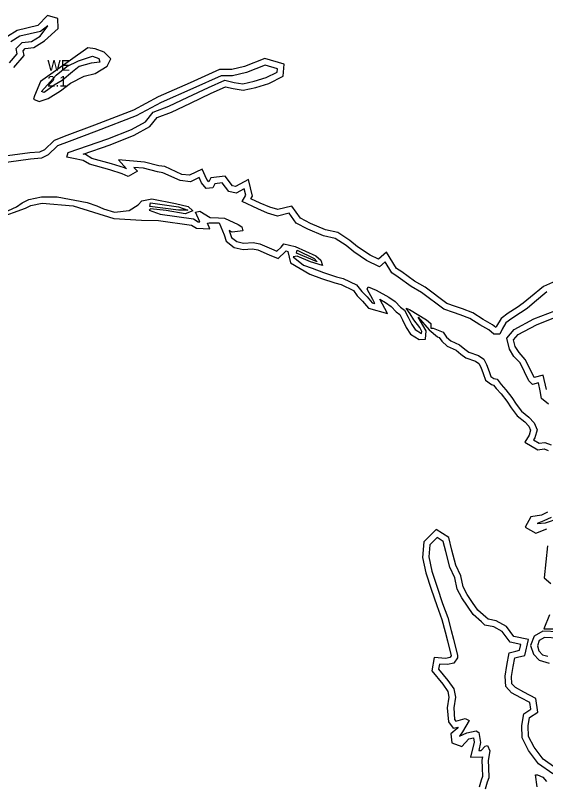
# Model space of a CAD drawing. Extents: x 2160437 to 2172832, y 205694 to 212444.
# Drawn here: x 2162368.8 to 2162620.3, y 210230.1 to 210593.8 of the extents above; entities that cross this region are included whole.
import ezdxf

# ---------------------------------------------------------------- set-up
doc = ezdxf.new("R2010")
doc.units = 0
for name, color, linetype in [('RD_EX_H2O', 7, 'Continuous'), ('RD_EX_H2O_Pond', 7, 'Continuous'), ('RD_EX_H2O_txCode', 7, 'Continuous'), ('RD_EX_VEG_ShrubLine', 7, 'Continuous')]:
    doc.layers.add(name, color=color, linetype=linetype)

msp = doc.modelspace()

# ---------------------------------------------------------------- linework, layer by layer
at = {"layer": 'RD_EX_H2O'}
for points in [[(2162366.04, 210571.34), (2162369.65, 210575.55), (2162369.15, 210578.05), (2162372.03, 210580.91), (2162376.47, 210581.45), (2162380.52, 210583.96), (2162384.23, 210588.79), (2162380.74, 210586.21), (2162370.89, 210583.87), (2162366.65, 210581.2)], [(2162535.39, 210477.67), (2162529.25, 210481.66), (2162525.66, 210484.63), (2162520.48, 210488.07), (2162514.92, 210489.34), (2162507.55, 210492.44), (2162501.91, 210495.25), (2162498.67, 210499.98), (2162493.1, 210498.63), (2162488.42, 210500.1), (2162483.72, 210502.07), (2162476.33, 210505.54), (2162478.05, 210508.61), (2162477.33, 210511.57), (2162473.57, 210509.58), (2162470.03, 210510.38), (2162466.9, 210514.4), (2162463.37, 210514), (2162462.4, 210512.09), (2162459.33, 210511.66), (2162457.05, 210514.35), (2162455.9, 210516.9), (2162451.92, 210514.95), (2162446.87, 210515.46), (2162438.76, 210519.18), (2162436.17, 210519.55), (2162429.52, 210521.31), (2162425.01, 210521.7), (2162426.66, 210519.88), (2162422.31, 210517.38), (2162419.48, 210518.7), (2162413.52, 210520.51), (2162403.88, 210523.24), (2162400.88, 210524.99), (2162396.28, 210525.96), (2162393.21, 210526.6), (2162393.87, 210528.76), (2162412.68, 210535.21), (2162423.85, 210539.71), (2162430.52, 210543.4), (2162434.19, 210547.88), (2162441.62, 210550.7), (2162450.52, 210554.95), (2162460.46, 210559.64), (2162468.2, 210563.04), (2162472.61, 210562.03), (2162476.69, 210561.36), (2162482, 210562.53), (2162487.81, 210564.27), (2162492.99, 210566.88), (2162493.11, 210568.51), (2162487.25, 210570.15), (2162478.33, 210566.68), (2162471.73, 210565.18), (2162466.32, 210565.13), (2162452.91, 210559.1), (2162437.86, 210552.49), (2162426.04, 210546.11), (2162407.33, 210538.96), (2162394.31, 210534.08), (2162388.8, 210531.92), (2162384.26, 210527.64), (2162381.1, 210526.05), (2162375.89, 210525.67), (2162360.88, 210523.59)], [(2162363.41, 210500.28), (2162369.37, 210503.03), (2162372, 210504.92), (2162375.17, 210506.51), (2162381.24, 210507.76), (2162388.62, 210507.78), (2162402.77, 210505.09), (2162407.4, 210503.51), (2162410.65, 210502.06), (2162415.85, 210500.53), (2162422.68, 210501.33), (2162427.04, 210504.01), (2162428.79, 210505.93), (2162433.48, 210506.9), (2162444.67, 210504.69), (2162450.77, 210503.18), (2162452.9, 210501.09), (2162449.28, 210499.7), (2162440.26, 210501.25), (2162432.87, 210502.02), (2162432.21, 210501.47), (2162437.45, 210499.5), (2162453.24, 210497.28), (2162455.53, 210495.96), (2162456.29, 210495.92), (2162454.27, 210500.54), (2162456.21, 210501), (2162461.15, 210497.96), (2162465.08, 210497.89), (2162468.03, 210497.66), (2162474.4, 210494.71), (2162476.21, 210493.54), (2162476.67, 210491.6), (2162471.62, 210491.03), (2162470.21, 210491.77), (2162471.29, 210488.54), (2162473.88, 210486.55), (2162477, 210485.88), (2162481.5, 210486.16), (2162484.69, 210485.52), (2162490.34, 210483.13), (2162492.82, 210482.09), (2162494.79, 210483.97), (2162496.05, 210485.45), (2162501.5, 210484.22), (2162511.34, 210479.79), (2162513.73, 210477.76), (2162514.49, 210475.15), (2162508.82, 210476.95), (2162502.42, 210479.68), (2162500.52, 210479.32), (2162505.46, 210475.33), (2162509.52, 210473.95), (2162514.96, 210471.89), (2162521.08, 210469.89), (2162524.31, 210469.05), (2162530.5, 210466)], [(2162620.81, 210462.75), (2162615, 210457.9), (2162611.46, 210454.91), (2162608.44, 210452.84), (2162604.18, 210450.11), (2162601.46, 210448.02), (2162599.59, 210445.02), (2162598.54, 210442.67), (2162595.65, 210442.63), (2162593.37, 210444.66), (2162589.04, 210447.06), (2162584.34, 210450.1), (2162579.77, 210451.82), (2162576.63, 210452.98), (2162571.97, 210454.5), (2162561.42, 210462.48), (2162556.44, 210465.29), (2162550.32, 210469.74), (2162547.41, 210471.69), (2162544.15, 210476.91), (2162541.51, 210474.6), (2162535.39, 210477.67)], [(2162530.5, 210466), (2162533.08, 210462.88), (2162535.62, 210460.37), (2162537.98, 210457.59), (2162539.32, 210457.23), (2162538.33, 210459.05), (2162535.64, 210464.08), (2162536.14, 210465.06), (2162539.93, 210463.61), (2162545.93, 210460.24), (2162548.94, 210458.12), (2162551.44, 210455.51), (2162553.42, 210454.04), (2162555.15, 210450.76), (2162556.83, 210447.25), (2162558.41, 210444.88), (2162561.4, 210442.95), (2162561.62, 210443.99), (2162560.65, 210445.86), (2162557.81, 210449.46), (2162556.08, 210452.32), (2162554.07, 210454.95), (2162555.74, 210454.39), (2162563.84, 210449.54), (2162565.86, 210447.75), (2162565.89, 210445.52), (2162566.92, 210445.54), (2162571.64, 210443.63), (2162573.32, 210441.32), (2162575.29, 210439.55), (2162579.47, 210437.64), (2162582, 210435.5), (2162583.85, 210434.14), (2162588.51, 210432.61), (2162590.92, 210430.76), (2162592.24, 210428.32), (2162593.54, 210425.04), (2162594.29, 210422.68), (2162595.79, 210421.59), (2162597.27, 210421.29), (2162599.18, 210418.83), (2162601.43, 210416.34), (2162604.3, 210412.67), (2162606.33, 210409.55), (2162608.89, 210406.14), (2162612.38, 210403.33), (2162614.91, 210400.65), (2162616.19, 210397.33), (2162615.19, 210393.58), (2162614.55, 210392.54), (2162617.15, 210390.97), (2162619.9, 210391.37), (2162622.95, 210390.14)], [(2162621.61, 210409.55), (2162618.35, 210412.19), (2162617.76, 210415.87), (2162616.88, 210419.55), (2162613.99, 210418.85), (2162612.32, 210420.5), (2162608.13, 210429.01), (2162605.26, 210432.14), (2162603.09, 210435.62), (2162601.82, 210440.73), (2162605.3, 210444.94), (2162614.74, 210449.87), (2162624.64, 210453.81)], [(2162622.86, 210355.72), (2162619.42, 210354.19), (2162616.29, 210352.94), (2162620.22, 210353.29), (2162626.75, 210355.44)], [(2162623.75, 210234.33), (2162616.94, 210238.97), (2162612.23, 210245.25), (2162609.09, 210251.26), (2162609.03, 210257.22), (2162609.93, 210262.76), (2162613.29, 210264.92), (2162612.82, 210268.06), (2162608.52, 210270.27), (2162604.09, 210272.71), (2162601.35, 210275.73), (2162601.13, 210280.62), (2162601.95, 210285.59), (2162603.02, 210291.65), (2162606.19, 210292.46), (2162607.87, 210292.85), (2162608.5, 210295.63), (2162603.52, 210296.7), (2162599.73, 210301.79), (2162595.73, 210303.86), (2162591.52, 210304.77), (2162589.93, 210306.32), (2162585.89, 210309.78), (2162583.16, 210313.75), (2162580.5, 210317.75), (2162578.35, 210321.82), (2162577.14, 210327.09), (2162574.87, 210332.23), (2162572.91, 210339.57), (2162571.75, 210344.4), (2162568.82, 210346.3), (2162565.38, 210342.85), (2162564.91, 210337.07), (2162566.33, 210330.26), (2162568.83, 210322.8), (2162571.43, 210315), (2162573.97, 210308.3), (2162575.55, 210302.27), (2162576.58, 210298.1), (2162578.5, 210290.41), (2162578.41, 210289.25), (2162576.71, 210286.77), (2162573.7, 210286.07), (2162569.94, 210286.24), (2162569.49, 210283.86), (2162573.9, 210278.55), (2162576.79, 210274.51), (2162577.46, 210270.62), (2162576.67, 210265.46), (2162577.09, 210260.05), (2162577.69, 210259.25), (2162582.17, 210260.44), (2162584.08, 210259.59), (2162580.89, 210254.17), (2162579.42, 210252.07), (2162582.92, 210253.75), (2162587.4, 210254.65), (2162588.64, 210253.8), (2162589.46, 210249.18), (2162588.52, 210245.28), (2162589.74, 210245.34), (2162591.56, 210247.29), (2162592.75, 210247.66), (2162593.8, 210245.16), (2162593.08, 210240.56), (2162593.23, 210237.26), (2162593.31, 210232.43), (2162592.52, 210230.26), (2162591.6, 210226.96)], [(2162626.29, 210298.59), (2162619.71, 210298.87), (2162617.29, 210297.48), (2162616.36, 210294.96), (2162617.13, 210292.52), (2162618.86, 210290.74), (2162621.37, 210290.04)], [(2162616.19, 210228.1), (2162615.52, 210233.73), (2162616.4, 210233.82), (2162618.98, 210232.62), (2162620.69, 210230.66)]]:
    msp.add_lwpolyline(points, dxfattribs=at)
at = {"layer": 'RD_EX_H2O_Pond'}
msp.add_lwpolyline([(2162381.22, 210557.68), (2162388.21, 210565.43), (2162393.12, 210569.6), (2162398.66, 210572.23), (2162405.3, 210574.5), (2162408.42, 210573.29), (2162408.89, 210571.64), (2162404.75, 210571.09), (2162399.03, 210569.55), (2162395.88, 210567.05), (2162391.02, 210562.86), (2162387.14, 210560.75), (2162382.45, 210557.2)], close=True, dxfattribs=at)
at = {"layer": 'RD_EX_VEG_ShrubLine'}
for points in [[(2162368.07, 210569.1), (2162372.88, 210574.71), (2162372.41, 210577.06), (2162373.41, 210578.05), (2162377.49, 210578.55), (2162382.57, 210581.7), (2162389.13, 210587.53), (2162388.92, 210592.27), (2162383.96, 210593.81), (2162379.45, 210588.98), (2162369.71, 210586.67), (2162365.05, 210583.74)], [(2162625.04, 210467.86), (2162619.22, 210465.33), (2162613.07, 210460.2), (2162609.64, 210457.3), (2162606.79, 210455.34), (2162602.46, 210452.57), (2162599.2, 210450.07), (2162596.93, 210446.43), (2162596.64, 210445.77), (2162595.12, 210447.12), (2162590.59, 210449.63), (2162585.7, 210452.79), (2162580.82, 210454.64), (2162577.61, 210455.81), (2162573.38, 210457.2), (2162563.07, 210464.99), (2162558.06, 210467.81), (2162552.04, 210472.2), (2162549.61, 210473.82), (2162544.83, 210481.48), (2162541.05, 210478.19), (2162537.02, 210480.19), (2162531.03, 210484.08), (2162527.45, 210487.04), (2162521.68, 210490.88), (2162515.85, 210492.21), (2162508.8, 210495.17), (2162503.94, 210497.59), (2162499.98, 210503.39), (2162493.2, 210501.74), (2162489.45, 210502.92), (2162484.94, 210504.82), (2162480.53, 210506.88), (2162481.25, 210508.17), (2162479.33, 210516.02), (2162473.15, 210512.75), (2162471.74, 210513.07), (2162468.24, 210517.58), (2162461.42, 210516.79), (2162460.48, 210514.94), (2162459.61, 210515.96), (2162457.37, 210520.95), (2162451.37, 210518.02), (2162447.67, 210518.39), (2162439.62, 210522.09), (2162436.77, 210522.5), (2162430.03, 210524.28), (2162417.64, 210525.33), (2162421.54, 210521.05), (2162420.56, 210521.51), (2162414.36, 210523.39), (2162405.06, 210526.02), (2162401.98, 210527.82), (2162400.99, 210528.03), (2162413.73, 210532.4), (2162425.14, 210537), (2162432.48, 210541.05), (2162436.01, 210545.36), (2162442.8, 210547.94), (2162451.81, 210552.24), (2162461.7, 210556.91), (2162468.5, 210559.89), (2162472.03, 210559.09), (2162476.77, 210558.31), (2162482.76, 210559.63), (2162488.92, 210561.47), (2162495.85, 210564.97), (2162496.29, 210570.73), (2162487.09, 210573.31), (2162477.45, 210569.56), (2162471.38, 210568.18), (2162465.66, 210568.13), (2162451.69, 210561.84), (2162436.54, 210555.19), (2162424.78, 210548.85), (2162406.27, 210541.77), (2162393.24, 210536.88), (2162387.16, 210534.5), (2162382.52, 210530.12), (2162380.28, 210529), (2162375.57, 210528.65), (2162360.15, 210526.51)], [(2162360.33, 210497.74), (2162373.56, 210502.34), (2162376.16, 210503.65), (2162381.55, 210504.76), (2162396.19, 210503.45), (2162415.45, 210497.54), (2162415.45, 210497.54), (2162428.54, 210496.7), (2162436.7, 210496.58), (2162452.25, 210494.39), (2162454.66, 210493), (2162460.99, 210492.68), (2162459.88, 210495.22), (2162460.77, 210495.52), (2162465.42, 210495.44), (2162467.75, 210489.69), (2162468.74, 210486.72), (2162472.59, 210483.75), (2162476.78, 210482.86), (2162481.3, 210483.14), (2162483.81, 210482.64), (2162489.18, 210480.36), (2162493.47, 210478.56), (2162496.98, 210481.9), (2162497.16, 210482.12), (2162498.08, 210481.92), (2162499.29, 210476.54), (2162508.5, 210471.12), (2162513.96, 210469.06), (2162520.24, 210467), (2162523.26, 210466.22), (2162529.18, 210463.31), (2162530.86, 210460.85), (2162533.42, 210458.33), (2162536.3, 210454.93), (2162545.29, 210452.55), (2162541.67, 210459.19), (2162544.32, 210457.7), (2162546.98, 210455.83), (2162549.45, 210453.26), (2162551.08, 210452.04), (2162552.46, 210449.41), (2162554.21, 210445.77), (2162556.26, 210442.69), (2162560.24, 210440.13), (2162563.38, 210440.24), (2162563.57, 210444.22), (2162559.88, 210450.66), (2162565.11, 210444.7), (2162568.94, 210441.48), (2162569.72, 210441.17), (2162571.08, 210439.3), (2162573.62, 210437.01), (2162577.85, 210435.08), (2162580.14, 210433.14), (2162582.46, 210431.43), (2162587.09, 210429.92), (2162588.59, 210428.77), (2162589.52, 210427.05), (2162590.72, 210424.04), (2162591.73, 210420.83), (2162594.56, 210418.78), (2162595.59, 210418.57), (2162596.88, 210416.91), (2162599.13, 210414.41), (2162601.85, 210410.92), (2162603.87, 210407.83), (2162606.72, 210404.03), (2162610.34, 210401.12), (2162612.32, 210399.02), (2162613.04, 210397.16), (2162612.41, 210394.78), (2162610.41, 210391.54), (2162616.52, 210387.85), (2162619.53, 210388.28), (2162621.42, 210387.52)], [(2162620.71, 210416.45), (2162619.1, 210423.18), (2162614.91, 210422.16), (2162614.79, 210422.28), (2162610.63, 210430.72), (2162607.66, 210433.96), (2162605.88, 210436.8), (2162605.1, 210439.99), (2162607.23, 210442.56), (2162615.99, 210447.14), (2162626.59, 210451.36)], [(2162621.23, 210358.28), (2162618.25, 210356.95), (2162613.24, 210356.16), (2162610.55, 210351.22), (2162615.57, 210348.33), (2162620.83, 210350.34)], [(2162625.17, 210237), (2162619.04, 210241.17), (2162614.78, 210246.86), (2162612.08, 210252.01), (2162612.03, 210256.99), (2162612.67, 210260.96), (2162616.54, 210263.45), (2162615.56, 210270.03), (2162609.93, 210272.92), (2162605.98, 210275.1), (2162604.3, 210276.94), (2162604.14, 210280.44), (2162604.91, 210285.08), (2162605.64, 210289.22), (2162606.91, 210289.54), (2162610.38, 210290.36), (2162612.1, 210297.92), (2162605.25, 210299.39), (2162601.72, 210304.14), (2162596.76, 210306.71), (2162592.99, 210307.52), (2162591.95, 210308.53), (2162588.14, 210311.81), (2162585.64, 210315.44), (2162583.08, 210319.29), (2162581.18, 210322.87), (2162580, 210328.04), (2162577.71, 210333.23), (2162575.82, 210340.31), (2162574.39, 210346.26), (2162568.42, 210350.13), (2162562.48, 210344.19), (2162561.88, 210336.88), (2162563.43, 210329.48), (2162565.99, 210321.85), (2162568.6, 210314), (2162571.11, 210307.39), (2162572.64, 210301.53), (2162573.67, 210297.37), (2162575.45, 210290.24), (2162574.89, 210289.43), (2162573.02, 210288.99), (2162573.02, 210288.99), (2162567.48, 210289.35), (2162566.27, 210283.03), (2162571.52, 210276.71), (2162573.95, 210273.33), (2162574.42, 210270.59), (2162573.65, 210265.57), (2162574.17, 210258.96), (2162576.5, 210255.83), (2162578.73, 210256.42), (2162578.37, 210255.8), (2162575.32, 210253.26), (2162575.87, 210248.87), (2162580.52, 210247.22), (2162583.88, 210250.89), (2162586.03, 210251.31), (2162586.4, 210249.27), (2162584.66, 210242.1), (2162590.32, 210242.36), (2162590.07, 210240.73), (2162590.23, 210237.17), (2162590.3, 210232.93), (2162589.67, 210231.18), (2162588.76, 210227.95)], [(2162621.17, 210342.28), (2162619.55, 210327.12), (2162622.77, 210324.54)], [(2162622.08, 210309.68), (2162619.38, 210302.99), (2162624.12, 210303.05)], [(2162626.46, 210301.58), (2162618.96, 210301.91), (2162614.86, 210299.54), (2162613.18, 210295.04), (2162614.48, 210290.94), (2162617.27, 210288.06), (2162621.97, 210286.76)]]:
    msp.add_lwpolyline(points, dxfattribs=at)
for points in [[(2162380.66, 210562.4), (2162377.87, 210555.72), (2162377.33, 210554.1), (2162380.03, 210553.02), (2162384.33, 210554.47), (2162390.26, 210557.95), (2162394.94, 210561.62), (2162401.44, 210564.91), (2162406.58, 210566.22), (2162412.26, 210569.69), (2162413.99, 210573.18), (2162410.88, 210576.43), (2162406.59, 210577.97), (2162403.11, 210578.38)], [(2162432.82, 210504.92), (2162446.17, 210503.05), (2162450.61, 210501.49), (2162446.1, 210501.42), (2162432.63, 210503.18)], [(2162502.36, 210482.51), (2162510.54, 210478.54), (2162512, 210476.98), (2162502.12, 210481.04)]]:
    msp.add_lwpolyline(points, close=True, dxfattribs=at)

# ---------------------------------------------------------------- texts
at = {"layer": 'RD_EX_H2O_txCode'}
for s, p in [('WE', (2162383.97, 210567.57)), ('2.1', (2162383.97, 210560.07))]:
    msp.add_text(s, height=5, dxfattribs=at).set_placement(p)

doc.saveas('drawing.dxf')
